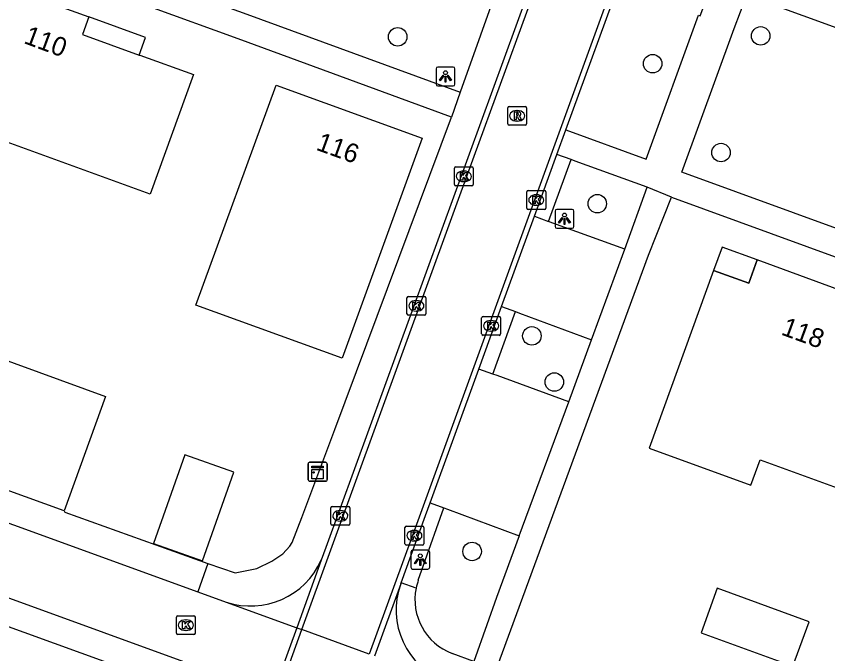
# Model space of a CAD drawing. Extents: x 155275 to 156263, y 382654 to 383635.
# Drawn here: x 155952.07 to 155994.99, y 382875.11 to 382908.85 of the extents above; entities that cross this region are included whole.
import ezdxf

# ---------------------------------------------------------------- set-up
doc = ezdxf.new("R2010")
doc.units = 0
for name, color, linetype in [('IMGEO_Boom', 7, 'Continuous'), ('IMGEO_Kast', 7, 'Continuous'), ('IMGEO_Kolk', 7, 'Continuous'), ('IMGEO_Lichtpunt', 7, 'Continuous'), ('IMGEO_Pand', 7, 'Continuous'), ('IMGEO_Pand_nummerreeks', 7, 'Continuous'), ('IMGEO_Pand_overbouw', 7, 'Continuous'), ('IMGEO_Parkeervlak_open', 7, 'Continuous'), ('IMGEO_Rijbaan_lokaal_gesloten', 7, 'Continuous'), ('IMGEO_Rijbaan_lokaal_open', 7, 'Continuous'), ('IMGEO_Rioolput', 7, 'Continuous'), ('IMGEO_Voetpad_open', 7, 'Continuous')]:
    doc.layers.add(name, color=color, linetype=linetype)

msp = doc.modelspace()

# ---------------------------------------------------------------- linework, layer by layer
at = {"layer": 'IMGEO_Boom'}
for centre in [(155972.247, 382907.764), (155991.447, 382907.815), (155985.731, 382906.343), (155989.348, 382901.64), (155982.803, 382898.931), (155979.343, 382891.936), (155980.529, 382889.492), (155976.184, 382880.524)]:
    msp.add_circle(centre, 0.489, dxfattribs=at)
at = {"layer": 'IMGEO_Kast'}
for p, q in [((155967.515, 382884.318), (155967.515, 382885.159)), ((155967.515, 382885.159), (155967.515, 382884.318)), ((155967.59, 382885.243), (155968.431, 382885.243)), ((155968.431, 382885.243), (155967.59, 382885.243)), ((155968.515, 382885.168), (155968.515, 382884.327)), ((155968.515, 382884.327), (155968.515, 382885.168)), ((155968.44, 382884.243), (155967.599, 382884.243)), ((155967.599, 382884.243), (155968.44, 382884.243))]:
    msp.add_line(p, q, dxfattribs=at)
for points in [[(155967.71, 382885.033), (155968.31, 382885.033), (155968.31, 382884.948), (155967.71, 382884.948), (155967.71, 382885.033)], [(155967.71, 382884.858), (155968.31, 382884.858), (155968.31, 382884.369), (155967.71, 382884.369), (155967.71, 382884.858)]]:
    msp.add_lwpolyline(points, dxfattribs=at)
msp.add_circle((155967.794, 382884.707), 0.0377, dxfattribs=at)
for centre, start, end in [((155967.593, 382885.165), 92.4484, 184.2845), ((155967.593, 382885.165), 92.4484, 184.2845), ((155968.437, 382885.165), 2.4484, 94.2845), ((155968.437, 382885.165), 2.4484, 94.2845), ((155967.593, 382884.321), 182.4484, 274.2845), ((155967.593, 382884.321), 182.4484, 274.2845), ((155968.437, 382884.321), 272.4484, 4.2845), ((155968.437, 382884.321), 272.4484, 4.2845)]:
    msp.add_arc(centre, 0.0779, start, end, dxfattribs=at)
at = {"layer": 'IMGEO_Kolk'}
for p, q in [((155975.245, 382899.954), (155975.245, 382900.806)), ((155975.32, 382900.88), (155976.172, 382900.88)), ((155975.733, 382900.66), (155975.758, 382900.66)), ((155976.246, 382900.806), (155976.246, 382899.954)), ((155976.172, 382899.88), (155975.32, 382899.88)), ((155975.756, 382900.1), (155975.731, 382900.1)), ((155979.077, 382898.7), (155979.077, 382899.552)), ((155979.152, 382899.626), (155980.004, 382899.626)), ((155979.565, 382899.406), (155979.59, 382899.406)), ((155980.078, 382899.552), (155980.078, 382898.7)), ((155980.004, 382898.626), (155979.152, 382898.626)), ((155979.588, 382898.846), (155979.563, 382898.846)), ((155972.734, 382893.102), (155972.734, 382893.954)), ((155972.809, 382894.028), (155973.661, 382894.028)), ((155973.222, 382893.808), (155973.247, 382893.808)), ((155973.735, 382893.954), (155973.735, 382893.102)), ((155973.661, 382893.028), (155972.809, 382893.028)), ((155973.245, 382893.248), (155973.22, 382893.248)), ((155976.688, 382892.039), (155976.688, 382892.891)), ((155976.763, 382892.965), (155977.615, 382892.965)), ((155977.689, 382892.891), (155977.689, 382892.039)), ((155977.176, 382892.745), (155977.201, 382892.745)), ((155977.199, 382892.185), (155977.174, 382892.185)), ((155977.615, 382891.965), (155976.763, 382891.965)), ((155968.712, 382881.983), (155968.712, 382882.835)), ((155968.787, 382882.909), (155969.639, 382882.909)), ((155969.2, 382882.689), (155969.225, 382882.689)), ((155969.713, 382882.835), (155969.713, 382881.983)), ((155969.639, 382881.909), (155968.787, 382881.909)), ((155969.223, 382882.129), (155969.198, 382882.129)), ((155972.63, 382880.937), (155972.63, 382881.789)), ((155972.705, 382881.863), (155973.557, 382881.863)), ((155973.631, 382881.789), (155973.631, 382880.937)), ((155973.118, 382881.643), (155973.143, 382881.643)), ((155973.557, 382880.863), (155972.705, 382880.863)), ((155973.141, 382881.083), (155973.116, 382881.083)), ((155960.542, 382876.2), (155960.542, 382877.052)), ((155960.617, 382877.126), (155961.469, 382877.126)), ((155961.543, 382877.052), (155961.543, 382876.2)), ((155961.03, 382876.906), (155961.055, 382876.906)), ((155961.053, 382876.346), (155961.028, 382876.346)), ((155961.469, 382876.126), (155960.617, 382876.126))]:
    msp.add_line(p, q, dxfattribs=at)
for points in [[(155975.245, 382899.954), (155975.245, 382900.806)], [(155975.32, 382900.88), (155976.172, 382900.88)], [(155976.246, 382900.806), (155976.246, 382899.954)], [(155975.566, 382900.58), (155975.689, 382900.58), (155975.689, 382900.429), (155975.819, 382900.58), (155975.983, 382900.58), (155975.837, 382900.429), (155975.99, 382900.18), (155975.838, 382900.18), (155975.753, 382900.344), (155975.689, 382900.277), (155975.689, 382900.18), (155975.566, 382900.18), (155975.566, 382900.58)], [(155976.172, 382899.88), (155975.32, 382899.88)], [(155979.077, 382898.7), (155979.077, 382899.552)], [(155979.152, 382899.626), (155980.004, 382899.626)], [(155979.398, 382899.326), (155979.521, 382899.326), (155979.521, 382899.175), (155979.651, 382899.326), (155979.815, 382899.326), (155979.669, 382899.175), (155979.822, 382898.926), (155979.67, 382898.926), (155979.585, 382899.09), (155979.521, 382899.023), (155979.521, 382898.926), (155979.398, 382898.926), (155979.398, 382899.326)], [(155980.078, 382899.552), (155980.078, 382898.7)], [(155980.004, 382898.626), (155979.152, 382898.626)], [(155972.734, 382893.102), (155972.734, 382893.954)], [(155972.809, 382894.028), (155973.661, 382894.028)], [(155973.055, 382893.728), (155973.178, 382893.728), (155973.178, 382893.577), (155973.308, 382893.728), (155973.472, 382893.728), (155973.326, 382893.577), (155973.479, 382893.328), (155973.327, 382893.328), (155973.242, 382893.492), (155973.178, 382893.425), (155973.178, 382893.328), (155973.055, 382893.328), (155973.055, 382893.728)], [(155973.735, 382893.954), (155973.735, 382893.102)], [(155973.661, 382893.028), (155972.809, 382893.028)], [(155976.688, 382892.039), (155976.688, 382892.891)], [(155976.763, 382892.965), (155977.615, 382892.965)], [(155977.689, 382892.891), (155977.689, 382892.039)], [(155977.009, 382892.665), (155977.132, 382892.665), (155977.132, 382892.514), (155977.262, 382892.665), (155977.426, 382892.665), (155977.28, 382892.514), (155977.433, 382892.265), (155977.281, 382892.265), (155977.196, 382892.429), (155977.132, 382892.362), (155977.132, 382892.265), (155977.009, 382892.265), (155977.009, 382892.665)], [(155977.615, 382891.965), (155976.763, 382891.965)], [(155968.712, 382881.983), (155968.712, 382882.835)], [(155968.787, 382882.909), (155969.639, 382882.909)], [(155969.033, 382882.609), (155969.156, 382882.609), (155969.156, 382882.458), (155969.286, 382882.609), (155969.45, 382882.609), (155969.304, 382882.458), (155969.457, 382882.209), (155969.305, 382882.209), (155969.22, 382882.373), (155969.156, 382882.306), (155969.156, 382882.209), (155969.033, 382882.209), (155969.033, 382882.609)], [(155969.713, 382882.835), (155969.713, 382881.983)], [(155969.639, 382881.909), (155968.787, 382881.909)], [(155972.63, 382880.937), (155972.63, 382881.789)], [(155972.705, 382881.863), (155973.557, 382881.863)], [(155973.631, 382881.789), (155973.631, 382880.937)], [(155972.951, 382881.563), (155973.074, 382881.563), (155973.074, 382881.412), (155973.204, 382881.563), (155973.368, 382881.563), (155973.222, 382881.412), (155973.375, 382881.163), (155973.223, 382881.163), (155973.138, 382881.327), (155973.074, 382881.26), (155973.074, 382881.163), (155972.951, 382881.163), (155972.951, 382881.563)], [(155973.557, 382880.863), (155972.705, 382880.863)], [(155960.542, 382876.2), (155960.542, 382877.052)], [(155960.617, 382877.126), (155961.469, 382877.126)], [(155961.543, 382877.052), (155961.543, 382876.2)], [(155960.863, 382876.826), (155960.986, 382876.826), (155960.986, 382876.675), (155961.116, 382876.826), (155961.28, 382876.826), (155961.134, 382876.675), (155961.287, 382876.426), (155961.135, 382876.426), (155961.05, 382876.59), (155960.986, 382876.523), (155960.986, 382876.426), (155960.863, 382876.426), (155960.863, 382876.826)], [(155961.469, 382876.126), (155960.617, 382876.126)]]:
    msp.add_lwpolyline(points, dxfattribs=at)
for centre, start, end in [((155975.322, 382900.804), 91.552, 178.448), ((155975.322, 382900.804), 91.552, 178.448), ((155976.17, 382900.804), 1.552, 88.448), ((155976.17, 382900.804), 1.552, 88.448), ((155975.322, 382899.956), 181.552, 268.448), ((155975.322, 382899.956), 181.552, 268.448), ((155976.17, 382899.956), 271.552, 358.448), ((155976.17, 382899.956), 271.552, 358.448), ((155979.154, 382899.55), 91.552, 178.448), ((155979.154, 382899.55), 91.552, 178.448), ((155980.002, 382899.55), 1.552, 88.448), ((155980.002, 382899.55), 1.552, 88.448), ((155979.154, 382898.702), 181.552, 268.448), ((155979.154, 382898.702), 181.552, 268.448), ((155980.002, 382898.702), 271.552, 358.448), ((155980.002, 382898.702), 271.552, 358.448), ((155972.811, 382893.952), 91.552, 178.448), ((155972.811, 382893.952), 91.552, 178.448), ((155973.659, 382893.952), 1.552, 88.448), ((155973.659, 382893.952), 1.552, 88.448), ((155972.811, 382893.104), 181.552, 268.448), ((155972.811, 382893.104), 181.552, 268.448), ((155973.659, 382893.104), 271.552, 358.448), ((155973.659, 382893.104), 271.552, 358.448), ((155976.765, 382892.889), 91.552, 178.448), ((155976.765, 382892.889), 91.552, 178.448), ((155977.613, 382892.889), 1.552, 88.448), ((155977.613, 382892.889), 1.552, 88.448), ((155976.765, 382892.041), 181.552, 268.448), ((155976.765, 382892.041), 181.552, 268.448), ((155977.613, 382892.041), 271.552, 358.448), ((155977.613, 382892.041), 271.552, 358.448), ((155968.789, 382882.833), 91.552, 178.448), ((155968.789, 382882.833), 91.552, 178.448), ((155969.637, 382882.833), 1.552, 88.448), ((155969.637, 382882.833), 1.552, 88.448), ((155968.789, 382881.985), 181.552, 268.448), ((155968.789, 382881.985), 181.552, 268.448), ((155969.637, 382881.985), 271.552, 358.448), ((155969.637, 382881.985), 271.552, 358.448), ((155972.707, 382881.787), 91.552, 178.448), ((155972.707, 382881.787), 91.552, 178.448), ((155973.555, 382881.787), 1.552, 88.448), ((155973.555, 382881.787), 1.552, 88.448), ((155972.707, 382880.939), 181.552, 268.448), ((155972.707, 382880.939), 181.552, 268.448), ((155973.555, 382880.939), 271.552, 358.448), ((155973.555, 382880.939), 271.552, 358.448), ((155960.619, 382877.05), 91.552, 178.448), ((155960.619, 382877.05), 91.552, 178.448), ((155961.467, 382877.05), 1.552, 88.448), ((155961.467, 382877.05), 1.552, 88.448), ((155960.619, 382876.202), 181.552, 268.448), ((155960.619, 382876.202), 181.552, 268.448), ((155961.467, 382876.202), 271.552, 358.448), ((155961.467, 382876.202), 271.552, 358.448)]:
    msp.add_arc(centre, 0.0765, start, end, dxfattribs=at)
for centre, major_axis, ratio, start_param, end_param in [((155975.732, 382900.38), (-0.387, 0.002), 0.722429, 4.712389, 7.853982), ((155975.757, 382900.38), (-0.39, 0.002), 0.717154, 1.570796, 4.712389), ((155979.564, 382899.126), (-0.387, 0.002), 0.722429, 4.712389, 7.853982), ((155979.589, 382899.126), (-0.39, 0.002), 0.717154, 1.570796, 4.712389), ((155973.221, 382893.528), (-0.387, 0.002), 0.722429, 4.712389, 7.853982), ((155973.246, 382893.528), (-0.39, 0.002), 0.717154, 1.570796, 4.712389), ((155977.175, 382892.465), (-0.387, 0.002), 0.722429, 4.712389, 7.853982), ((155977.2, 382892.465), (-0.39, 0.002), 0.717154, 1.570796, 4.712389), ((155969.199, 382882.409), (-0.387, 0.002), 0.722429, 4.712389, 7.853982), ((155969.224, 382882.409), (-0.39, 0.002), 0.717154, 1.570796, 4.712389), ((155973.117, 382881.363), (-0.387, 0.002), 0.722429, 4.712389, 7.853982), ((155973.142, 382881.363), (-0.39, 0.002), 0.717154, 1.570796, 4.712389), ((155961.029, 382876.626), (-0.387, 0.002), 0.722429, 4.712389, 7.853982), ((155961.054, 382876.626), (-0.39, 0.002), 0.717154, 1.570796, 4.712389)]:
    msp.add_ellipse(centre, major_axis=major_axis, ratio=ratio, start_param=start_param, end_param=end_param, dxfattribs=at)
at = {"layer": 'IMGEO_Lichtpunt'}
for p, q in [((155974.274, 382906.069), (155974.274, 382905.262)), ((155974.274, 382906.069), (155974.274, 382905.262)), ((155975.176, 382906.164), (155974.368, 382906.164)), ((155975.176, 382906.164), (155974.368, 382906.164)), ((155975.27, 382905.262), (155975.27, 382906.069)), ((155975.27, 382905.262), (155975.27, 382906.069)), ((155974.368, 382905.168), (155975.176, 382905.168)), ((155974.368, 382905.168), (155975.176, 382905.168)), ((155980.57, 382898.534), (155980.57, 382897.727)), ((155980.57, 382898.534), (155980.57, 382897.727)), ((155981.472, 382898.629), (155980.664, 382898.629)), ((155981.472, 382898.629), (155980.664, 382898.629)), ((155981.566, 382897.727), (155981.566, 382898.534)), ((155981.566, 382897.727), (155981.566, 382898.534)), ((155980.664, 382897.633), (155981.472, 382897.633)), ((155980.664, 382897.633), (155981.472, 382897.633)), ((155972.942, 382880.494), (155972.942, 382879.687)), ((155972.942, 382880.494), (155972.942, 382879.687)), ((155973.844, 382880.589), (155973.036, 382880.589)), ((155973.844, 382880.589), (155973.036, 382880.589)), ((155973.938, 382879.687), (155973.938, 382880.494)), ((155973.938, 382879.687), (155973.938, 382880.494)), ((155973.036, 382879.593), (155973.844, 382879.593)), ((155973.036, 382879.593), (155973.844, 382879.593))]:
    msp.add_line(p, q, dxfattribs=at)
for points in [[(155974.648, 382905.733), (155974.687, 382905.705), (155974.499, 382905.443), (155974.461, 382905.47), (155974.648, 382905.733)], [(155974.75, 382905.685), (155974.797, 382905.685), (155974.797, 382905.363), (155974.75, 382905.363), (155974.75, 382905.685)], [(155974.86, 382905.705), (155974.898, 382905.732), (155975.085, 382905.47), (155975.046, 382905.442), (155974.86, 382905.705)], [(155980.944, 382898.198), (155980.983, 382898.17), (155980.795, 382897.908), (155980.757, 382897.935), (155980.944, 382898.198)], [(155981.046, 382898.15), (155981.093, 382898.15), (155981.093, 382897.828), (155981.046, 382897.828), (155981.046, 382898.15)], [(155981.156, 382898.17), (155981.194, 382898.197), (155981.381, 382897.935), (155981.342, 382897.907), (155981.156, 382898.17)], [(155973.316, 382880.158), (155973.355, 382880.13), (155973.167, 382879.868), (155973.129, 382879.895), (155973.316, 382880.158)], [(155973.418, 382880.11), (155973.465, 382880.11), (155973.465, 382879.788), (155973.418, 382879.788), (155973.418, 382880.11)], [(155973.528, 382880.13), (155973.566, 382880.157), (155973.753, 382879.895), (155973.714, 382879.867), (155973.528, 382880.13)]]:
    msp.add_lwpolyline(points, dxfattribs=at)
for centre in [(155974.773, 382905.867), (155981.069, 382898.332), (155973.441, 382880.292)]:
    msp.add_circle(centre, 0.0994, dxfattribs=at)
for centre, start, end in [((155974.368, 382906.069), 90, 180), ((155974.368, 382906.069), 90, 180), ((155975.176, 382906.069), 0, 90), ((155975.176, 382906.069), 0, 90), ((155974.368, 382905.262), 180, 270), ((155974.368, 382905.262), 180, 270), ((155975.176, 382905.262), 270, 0), ((155975.176, 382905.262), 270, 360), ((155980.664, 382898.534), 90, 180), ((155980.664, 382898.534), 90, 180), ((155981.472, 382898.534), 0, 90), ((155981.472, 382898.534), 0, 90), ((155980.664, 382897.727), 180, 270), ((155980.664, 382897.727), 180, 270), ((155981.472, 382897.727), 270, 0), ((155981.472, 382897.727), 270, 360), ((155973.036, 382880.494), 90, 180), ((155973.036, 382880.494), 90, 180), ((155973.844, 382880.494), 0, 90), ((155973.844, 382880.494), 0, 90), ((155973.036, 382879.687), 180, 270), ((155973.036, 382879.687), 180, 270), ((155973.844, 382879.687), 270, 0), ((155973.844, 382879.687), 270, 360)]:
    msp.add_arc(centre, 0.0946, start, end, dxfattribs=at)
at = {"layer": 'IMGEO_Pand'}
for points in [[(155946.532, 382904.015), (155949.068, 382910.933), (155952.992, 382909.515), (155953.114, 382909.847), (155955.905, 382908.822), (155955.571, 382907.883), (155958.568, 382906.802), (155958.616, 382906.785), (155961.447, 382905.762), (155959.155, 382899.44), (155946.532, 382904.015)], [(155965.822, 382905.2), (155973.534, 382902.409), (155969.307, 382890.762), (155961.571, 382893.558), (155965.822, 382905.2)], [(155988.959, 382895.398), (155985.546, 382885.999), (155990.931, 382884.036), (155991.419, 382885.37), (155996.458, 382883.54), (155998.442, 382889.005), (155997.305, 382889.421), (155998.7, 382893.234), (155991.267, 382895.953), (155990.817, 382894.723), (155988.959, 382895.398)], [(155948.645, 382884.835), (155950.836, 382890.892), (155956.798, 382888.735), (155954.606, 382882.673)], [(155959.332, 382880.948), (155961.931, 382880.033), (155963.586, 382884.73), (155960.983, 382885.647), (155959.332, 382880.948)], [(155954.606, 382882.673), (155948.645, 382884.835)], [(155989.139, 382878.588), (155988.29, 382876.225), (155993.15, 382874.45), (155994.012, 382876.808), (155989.139, 382878.588)]]:
    msp.add_lwpolyline(points, dxfattribs=at)
at = {"layer": 'IMGEO_Pand_overbouw'}
for points in [[(155955.905, 382908.822), (155955.571, 382907.883), (155958.568, 382906.802), (155958.905, 382907.732)], [(155988.959, 382895.398), (155990.817, 382894.723), (155991.267, 382895.953), (155989.408, 382896.636)]]:
    msp.add_lwpolyline(points, close=True, dxfattribs=at)
at = {"layer": 'IMGEO_Parkeervlak_open'}
for points in [[(155984.256, 382896.523), (155980.451, 382897.9), (155980.223, 382897.987)], [(155978.482, 382893.218), (155978.684, 382893.142), (155982.505, 382891.726)], [(155981.293, 382888.444), (155977.51, 382889.832), (155977.282, 382889.911)], [(155974.691, 382882.827), (155974.885, 382882.755), (155978.68, 382881.361)]]:
    msp.add_lwpolyline(points, dxfattribs=at)
at = {"layer": 'IMGEO_Rijbaan_lokaal_gesloten'}
for points in [[(155967.181, 382876.387), (155968.713, 382880.618), (155976.296, 382901.446), (155981.859, 382916.715), (155988.961, 382936.106), (155990.869, 382941.386)], [(155994.401, 382940.096), (155992.82, 382935.75), (155984.021, 382911.618), (155973.447, 382882.532), (155970.743, 382875.09)], [(155989.298, 382937.8), (155988.716, 382936.177), (155981.583, 382916.812), (155976.023, 382901.548), (155968.442, 382880.729), (155968.205, 382880.073)], [(155981.138, 382902.838), (155984.29, 382911.513), (155984.547, 382912.217)], [(155980.662, 382901.529), (155981.138, 382902.838)], [(155979.479, 382898.272), (155980.662, 382901.529)], [(155977.743, 382893.496), (155979.479, 382898.272)], [(155976.535, 382890.17), (155977.743, 382893.496)], [(155973.964, 382883.095), (155976.535, 382890.17)], [(155972.423, 382878.859), (155973.722, 382882.429), (155973.964, 382883.095)], [(155968.205, 382880.073), (155966.906, 382876.487)], [(155972.405, 382878.81), (155971.015, 382874.99)], [(155972.405, 382878.81), (155972.423, 382878.859)], [(155966.906, 382876.487), (155965.631, 382872.963)], [(155965.905, 382872.862), (155967.181, 382876.387)], [(155966.906, 382876.487), (155967.181, 382876.387)]]:
    msp.add_lwpolyline(points, dxfattribs=at)
at = {"layer": 'IMGEO_Rijbaan_lokaal_open'}
for points in [[(155880.59, 382907.807), (155883.262, 382906.894), (155961.679, 382878.39)], [(155879.327, 382904.418), (155961.883, 382874.346)], [(155961.679, 382878.39), (155963.18, 382877.844)], [(155963.18, 382877.844), (155966.906, 382876.487)], [(155970.743, 382875.09), (155967.181, 382876.387)]]:
    msp.add_lwpolyline(points, dxfattribs=at)
for centre, radius, start, end in [((155964.467, 382881.722), 4.085, 251.64, 336.2024), ((155976.248, 382877.429), 4.083, 160.2394, 248.7351)]:
    msp.add_arc(centre, radius, start, end, dxfattribs=at)
at = {"layer": 'IMGEO_Rioolput'}
for p, q in [((155978.139, 382904.084), (155978.991, 382904.084)), ((155978.064, 382903.158), (155978.064, 382904.01)), ((155978.552, 382903.864), (155978.577, 382903.864)), ((155979.065, 382904.01), (155979.065, 382903.158)), ((155978.575, 382903.304), (155978.55, 382903.304)), ((155978.991, 382903.084), (155978.139, 382903.084))]:
    msp.add_line(p, q, dxfattribs=at)
for points in [[(155978.139, 382904.084), (155978.991, 382904.084)], [(155978.064, 382903.158), (155978.064, 382904.01)], [(155978.653, 382903.782), (155978.401, 382903.784), (155978.401, 382903.384)], [(155978.579, 382903.703), (155978.525, 382903.703), (155978.525, 382903.622)], [(155978.525, 382903.622), (155978.577, 382903.622)], [(155979.065, 382904.01), (155979.065, 382903.158)], [(155978.401, 382903.384), (155978.525, 382903.384), (155978.525, 382903.546), (155978.536, 382903.546)], [(155978.583, 382903.517), (155978.654, 382903.384), (155978.794, 382903.384), (155978.729, 382903.51)], [(155978.991, 382903.084), (155978.139, 382903.084)]]:
    msp.add_lwpolyline(points, dxfattribs=at)
for centre, radius, start, end in [((155978.141, 382904.008), 0.0765, 91.552, 178.448), ((155978.141, 382904.008), 0.0765, 91.552, 178.448), ((155978.989, 382904.008), 0.0765, 1.552, 88.448), ((155978.989, 382904.008), 0.0765, 1.552, 88.448), ((155978.561, 382903.811), 0.19, 274.7715, 282.9687), ((155978.585, 382903.607), 0.0964, 77.0061, 93.1865), ((155978.599, 382903.664), 0.0378, 276.6634, 79.6772), ((155978.652, 382903.672), 0.109, 350.3612, 89.416), ((155978.65, 382903.672), 0.112, 277.5842, 350.9817), ((155978.535, 382903.493), 0.0533, 26.0293, 88.6989), ((155978.634, 382903.457), 0.108, 29.5134, 73.7905), ((155978.141, 382903.16), 0.0765, 181.552, 268.448), ((155978.141, 382903.16), 0.0765, 181.552, 268.448), ((155978.989, 382903.16), 0.0765, 271.552, 358.448), ((155978.989, 382903.16), 0.0765, 271.552, 358.448)]:
    msp.add_arc(centre, radius, start, end, dxfattribs=at)
for centre, major_axis, ratio, start_param, end_param in [((155978.551, 382903.584), (-0.387, 0.002), 0.722429, 4.712389, 7.853982), ((155978.576, 382903.584), (-0.39, 0.002), 0.717154, 1.570796, 4.712389)]:
    msp.add_ellipse(centre, major_axis=major_axis, ratio=ratio, start_param=start_param, end_param=end_param, dxfattribs=at)
at = {"layer": 'IMGEO_Voetpad_open'}
for points in [[(155978.873, 382914.157), (155957.461, 382921.91), (155954.088, 382912.643), (155964.267, 382908.962), (155975.556, 382904.842)], [(155975.085, 382903.519), (155963.808, 382907.656), (155935.757, 382917.844)], [(155978.873, 382914.157), (155975.556, 382904.842)], [(155981.138, 382902.838), (155985.388, 382901.29), (155988.159, 382908.904), (155988.243, 382908.873), (155988.891, 382910.63), (155984.547, 382912.217)], [(156007.66, 382893.178), (155987.272, 382900.604), (155990.043, 382908.212), (155990.706, 382909.982), (156011.067, 382902.579), (156007.66, 382893.178)], [(155975.556, 382904.842), (155975.085, 382903.519)], [(155962.207, 382879.881), (155963.654, 382879.4), (155964.795, 382879.631), (155965.592, 382880.01), (155966.17, 382880.408), (155966.548, 382880.807), (155966.671, 382880.994), (155967.174, 382882.325), (155968.914, 382886.988), (155975.085, 382903.519)], [(155879.75, 382902.636), (155961.133, 382873.112)], [(155981.414, 382901.263), (155980.662, 382901.529)], [(155980.223, 382897.987), (155981.414, 382901.263)], [(155985.435, 382899.805), (155981.631, 382901.186), (155981.414, 382901.263)], [(155984.256, 382896.523), (155985.435, 382899.805)], [(155986.733, 382899.275), (155985.435, 382899.805)], [(155977.474, 382874.314), (155985.513, 382896.209), (155986.733, 382899.275)], [(155986.733, 382899.275), (156049.271, 382876.469)], [(155979.479, 382898.272), (155980.223, 382897.987)], [(155982.505, 382891.726), (155984.256, 382896.523)], [(155977.743, 382893.496), (155978.482, 382893.218)], [(155977.282, 382889.911), (155978.482, 382893.218)], [(155981.293, 382888.444), (155982.505, 382891.726)], [(155977.282, 382889.911), (155976.535, 382890.17)], [(155978.68, 382881.361), (155981.293, 382888.444)], [(155973.964, 382883.095), (155974.691, 382882.827)], [(155954.606, 382882.673), (155954.644, 382882.601), (155962.207, 382879.881)], [(155973.338, 382878.998), (155973.612, 382879.805), (155974.691, 382882.827)], [(155978.68, 382881.361), (155977.473, 382878.089), (155976.958, 382876.636), (155976.275, 382874.707), (155975.121, 382875.129)], [(155962.207, 382879.881), (155961.679, 382878.39)], [(155973.223, 382878.59), (155972.423, 382878.859)]]:
    msp.add_lwpolyline(points, dxfattribs=at)
for centre, radius, start, end in [((155976.062, 382878.01), 2.898, 160.0645, 168.4532), ((155976.201, 382877.972), 3.041, 168.2766, 249.2038)]:
    msp.add_arc(centre, radius, start, end, dxfattribs=at)

# ---------------------------------------------------------------- texts
at = {"layer": 'IMGEO_Pand_nummerreeks'}
for s, rotation, p in [('110', 339.6371, (155952.421, 382907.443)), ('116', 340.1081, (155967.878, 382901.797)), ('118', 339.9074, (155992.481, 382892.016))]:
    msp.add_text(s, height=1, rotation=rotation, dxfattribs=at).set_placement(p)

doc.saveas('drawing.dxf')
